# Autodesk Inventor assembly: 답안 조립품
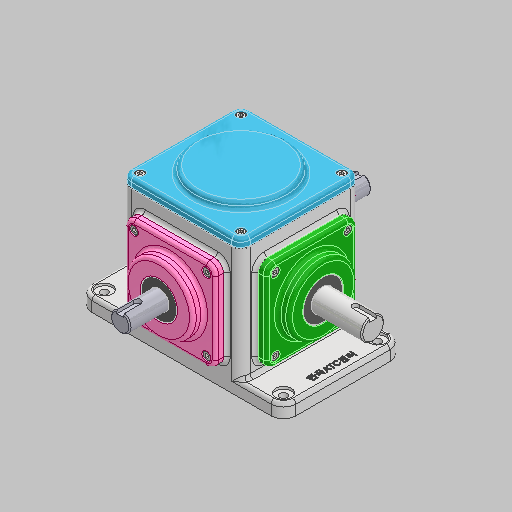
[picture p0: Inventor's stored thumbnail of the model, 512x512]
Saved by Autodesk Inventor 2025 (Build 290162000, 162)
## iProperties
Created: 2024-08
Part Number: 답안 조립품
Document SubType Name: Assembly
Designer: 현기
Author: 현기
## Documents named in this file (16)
- C:\Users\현기\Desktop\640807V1005\답안 조립품.iam
- C:\Users\현기\Desktop\640807V1005\본체\본체.ipt
- C:\Users\현기\Desktop\640807V1005\개스킷\개스킷.ipt
- C:\Users\현기\Desktop\640807V1005\메인베벨기어\메인베벨기어.ipt
- C:\Users\현기\Desktop\640807V1005\메인축\메인축.ipt
- C:\Users\현기\Desktop\640807V1005\메인커버\메인커버.ipt
- C:\Users\현기\Desktop\640807V1005\베어링 6203\베어링 6203.ipt
- C:\Users\현기\Desktop\640807V1005\베어링 6204\베어링 6204.ipt
- C:\Users\현기\Desktop\640807V1005\볼트 M4\볼트 M4.ipt
- C:\Users\현기\Desktop\640807V1005\상부커버\상부커버.ipt
- C:\Users\현기\Desktop\640807V1005\서브베벨기어\서브베벨기어.ipt
- C:\Users\현기\Desktop\640807V1005\서브축\서브축.ipt
- C:\Users\현기\Desktop\640807V1005\서브커버\서브커버.ipt
- C:\Users\현기\Desktop\640807V1005\오일 실 17 32 8\오일 실 17 32 8.ipt
- C:\Users\현기\Desktop\640807V1005\오일 실 20 35 8\오일 실 20 35 8.ipt
- C:\Users\현기\Desktop\640807V1005\키 4x4\키 4x4.ipt
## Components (1 placed, 1 different names)
1. 개스킷:1
